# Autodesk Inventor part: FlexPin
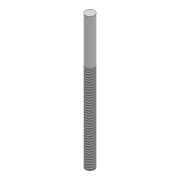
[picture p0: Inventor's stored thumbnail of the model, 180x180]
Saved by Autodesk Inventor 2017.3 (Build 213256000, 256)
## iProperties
Part Number: FlexPin
Material: 一般
Document SubType Name: Modeling
Designer: kyushu-hep
Density: 1 g/cm^3
Appearance: 既定
Author: kyushu-hep
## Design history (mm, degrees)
sketch "スケッチ1"
  geometry: C1 r 0.5 at (0, 0); 1 further point
  constraints: 1 centre point, 1 coincident
  dimensions: "d0" = 1 diameter of C1
extrude "押し出し1" new body sketch "スケッチ1" distance "d1" = 15; taper "d2" = 0 deg
feature "ねじ1" dims "d3" = 10, "d4" = 0
node "ソリッド1"
